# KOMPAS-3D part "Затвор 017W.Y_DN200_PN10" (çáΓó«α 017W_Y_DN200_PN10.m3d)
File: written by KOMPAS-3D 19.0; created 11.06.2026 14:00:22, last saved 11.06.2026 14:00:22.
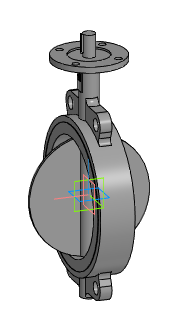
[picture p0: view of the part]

Document properties: Автор: Евгений; Полное имя файла: Z:\3.Личные\kachalov\001_3d для проектировщиков\x.x Тип 017W.Y(S) Затвор дисковый поворотный межфланцевый\_stp_Затвор 017W.Y_DN50-DN350\Затвор 017W_Y_DN200_PN10.m3d

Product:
- Part/product: Затвор 017W.Y_DN200_PN10

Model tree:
1. Операция без истории:1  (labels: Затвор 017W.Y_DN200_PN10)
